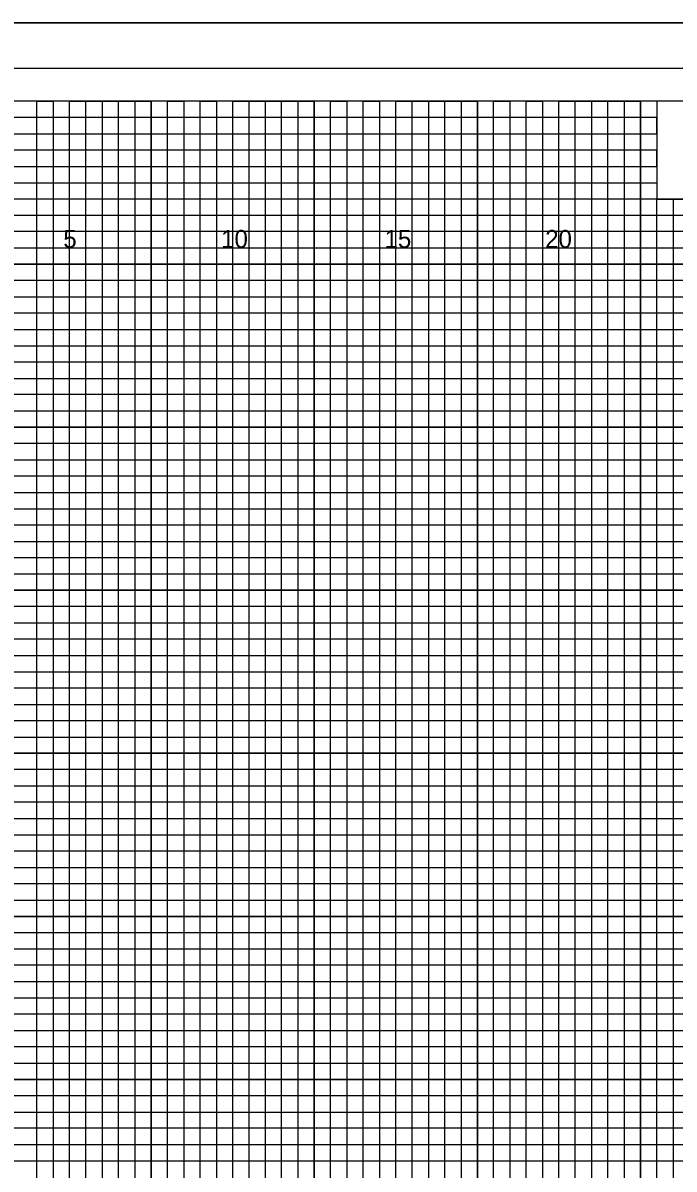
# Model space of a CAD drawing. Extents: x -4 to 103, y -2 to 138.
# Drawn here: x 54.82 to 74.78, y 103.08 to 138.22 of the extents above; entities that cross this region are included whole.
import ezdxf

# ---------------------------------------------------------------- set-up
doc = ezdxf.new("R2010")
doc.units = 0
for name, color, linetype in [('Old_Level_10', 7, 'Continuous'), ('Old_Level_16', 7, 'Continuous'), ('Old_Level_3', 7, 'Continuous'), ('Old_Level_4', 7, 'Continuous'), ('Old_Level_5', 7, 'Continuous'), ('Old_Level_8', 7, 'Continuous'), ('Prop Dimension', 7, 'Continuous'), ('Prop XS SE Text', 7, 'Continuous')]:
    doc.layers.add(name, color=color, linetype=linetype)

msp = doc.modelspace()

# ---------------------------------------------------------------- linework, layer by layer
at = {"layer": 'Old_Level_10'}
for p, q in [((56.25, 70.825), (56.25, 135.825)), ((58.75, 70.825), (58.75, 135.825)), ((61.25, 70.825), (61.25, 135.825)), ((63.75, 70.825), (63.75, 135.825)), ((66.25, 70.825), (66.25, 135.825)), ((68.75, 70.825), (68.75, 135.825)), ((71.25, 70.825), (71.25, 135.825)), ((73.75, 70.825), (73.75, 135.825)), ((0, 133.325), (74.25, 133.325)), ((0, 130.825), (102.5, 130.825)), ((0, 128.325), (102.5, 128.325)), ((0, 125.825), (102.5, 125.825)), ((0, 123.325), (102.5, 123.325)), ((0, 120.825), (102.5, 120.825)), ((0, 118.325), (102.5, 118.325)), ((0, 115.825), (102.5, 115.825)), ((0, 113.325), (102.5, 113.325)), ((0, 110.825), (102.5, 110.825)), ((0, 108.325), (102.5, 108.325)), ((0, 105.825), (102.5, 105.825)), ((0, 103.325), (102.5, 103.325))]:
    msp.add_line(p, q, dxfattribs=at)
at = {"layer": 'Old_Level_3'}
msp.add_line((-3.5, 138.225), (103.4, 138.225), dxfattribs=at)
at = {"layer": 'Old_Level_4'}
msp.add_lwpolyline([(103, 136.825), (-2.8, 136.825), (-2.8, 69.825), (103, 69.825)], close=True, dxfattribs=at)
at = {"layer": 'Old_Level_5'}
msp.add_lwpolyline([(103.4, 138.225), (-3.5, 138.225), (-3.5, 68.4), (103.4, 68.4)], close=True, dxfattribs=at)
at = {"layer": 'Old_Level_8'}
for points in [[(56.25, 70.825), (56.25, 135.825), (58.75, 135.825), (58.75, 70.825)], [(61.25, 70.825), (61.25, 135.825), (63.75, 135.825), (63.75, 70.825)], [(66.25, 70.825), (66.25, 135.825), (68.75, 135.825), (68.75, 70.825)], [(71.25, 70.825), (71.25, 135.825), (73.75, 135.825), (73.75, 70.825)], [(0, 133.325), (74.25, 133.325)], [(0, 128.325), (102.5, 128.325), (102.5, 130.825), (0, 130.825)], [(0, 123.325), (102.5, 123.325), (102.5, 125.825), (0, 125.825)], [(0, 118.325), (102.5, 118.325), (102.5, 120.825), (0, 120.825)], [(0, 113.325), (102.5, 113.325), (102.5, 115.825), (0, 115.825)], [(0, 108.325), (102.5, 108.325), (102.5, 110.825), (0, 110.825)], [(0, 103.325), (102.5, 103.325), (102.5, 105.825), (0, 105.825)]]:
    msp.add_lwpolyline(points, dxfattribs=at)
at = {"layer": 'Prop Dimension'}
for points in [[(55.25, 70.825), (55.25, 135.825), (55.75, 135.825), (55.75, 70.825)], [(56.75, 70.825), (56.75, 135.825), (57.25, 135.825), (57.25, 70.825)], [(57.75, 70.825), (57.75, 135.825), (58.25, 135.825), (58.25, 70.825)], [(59.25, 70.825), (59.25, 135.825), (59.75, 135.825), (59.75, 70.825)], [(60.25, 70.825), (60.25, 135.825), (60.75, 135.825), (60.75, 70.825)], [(61.75, 70.825), (61.75, 135.825), (62.25, 135.825), (62.25, 70.825)], [(62.75, 70.825), (62.75, 135.825), (63.25, 135.825), (63.25, 70.825)], [(64.25, 70.825), (64.25, 135.825), (64.75, 135.825), (64.75, 70.825)], [(65.25, 70.825), (65.25, 135.825), (65.75, 135.825), (65.75, 70.825)], [(66.75, 70.825), (66.75, 135.825), (67.25, 135.825), (67.25, 70.825)], [(67.75, 70.825), (67.75, 135.825), (68.25, 135.825), (68.25, 70.825)], [(69.25, 70.825), (69.25, 135.825)], [(69.25, 135.825), (69.75, 135.825), (69.75, 70.825)], [(70.25, 70.825), (70.25, 135.825), (70.75, 135.825), (70.75, 70.825)], [(71.75, 70.825), (71.75, 135.825), (72.25, 135.825), (72.25, 70.825)], [(72.75, 70.825), (72.75, 135.825), (73.25, 135.825), (73.25, 70.825)], [(0, 132.825), (0, 133.825), (74.25, 133.825), (74.25, 134.325), (0, 134.325), (0, 134.825), (74.25, 134.825), (74.25, 135.325), (0, 135.325)], [(0, 132.325), (102.5, 132.325), (102.5, 132.825), (0, 132.825)], [(74.25, 70.825), (74.25, 132.825), (74.75, 132.825), (74.75, 70.825)], [(0, 131.325), (102.5, 131.325), (102.5, 131.825), (0, 131.825)], [(0, 129.825), (102.5, 129.825), (102.5, 130.325), (0, 130.325)], [(0, 128.825), (102.5, 128.825), (102.5, 129.325), (0, 129.325)], [(0, 127.325), (102.5, 127.325), (102.5, 127.825), (0, 127.825)], [(0, 126.325), (102.5, 126.325), (102.5, 126.825), (0, 126.825)], [(0, 124.825), (102.5, 124.825), (102.5, 125.325), (0, 125.325)], [(0, 123.825), (102.5, 123.825), (102.5, 124.325), (0, 124.325)], [(0, 122.325), (102.5, 122.325), (102.5, 122.825), (0, 122.825)], [(0, 121.325), (102.5, 121.325), (102.5, 121.825), (0, 121.825)], [(0, 119.825), (102.5, 119.825), (102.5, 120.325), (0, 120.325)], [(0, 118.825), (102.5, 118.825), (102.5, 119.325), (0, 119.325)], [(0, 117.325), (102.5, 117.325), (102.5, 117.825), (0, 117.825)], [(0, 116.325), (102.5, 116.325), (102.5, 116.825), (0, 116.825)], [(0, 114.825), (102.5, 114.825), (102.5, 115.325), (0, 115.325)], [(0, 113.825), (102.5, 113.825), (102.5, 114.325), (0, 114.325)], [(0, 112.325), (102.5, 112.325), (102.5, 112.825), (0, 112.825)], [(0, 111.325), (102.5, 111.325), (102.5, 111.825), (0, 111.825)], [(0, 109.825), (102.5, 109.825), (102.5, 110.325), (0, 110.325)], [(0, 108.825), (102.5, 108.825), (102.5, 109.325), (0, 109.325)], [(0, 107.325), (102.5, 107.325), (102.5, 107.825), (0, 107.825)], [(0, 106.325), (102.5, 106.325), (102.5, 106.825), (0, 106.825)], [(0, 104.825), (102.5, 104.825), (102.5, 105.325), (0, 105.325)], [(0, 103.825), (102.5, 103.825), (102.5, 104.325), (0, 104.325)]]:
    msp.add_lwpolyline(points, dxfattribs=at)
at = {"layer": 'Prop XS SE Text'}
for points in [[(102.5, 135.825), (0, 135.825), (0, 70.825), (102.5, 70.825)], [(83.75, 135.825), (74.25, 135.825), (74.25, 132.825), (83.75, 132.825)]]:
    msp.add_lwpolyline(points, close=True, dxfattribs=at)

# ---------------------------------------------------------------- texts
at = {"layer": 'Old_Level_16'}
for s, p in [('5', (56.0574, 131.325)), ('10', (60.8971, 131.325)), ('15', (65.9057, 131.325)), ('20', (70.8312, 131.325))]:
    msp.add_text(s, height=0.55, dxfattribs=at).set_placement(p)

doc.saveas('drawing.dxf')
